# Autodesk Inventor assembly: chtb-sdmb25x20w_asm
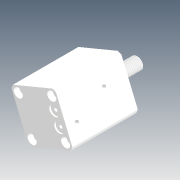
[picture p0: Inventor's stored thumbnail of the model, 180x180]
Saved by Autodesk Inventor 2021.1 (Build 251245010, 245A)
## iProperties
Company: Microsoft
Created: 2018-05
Part Number: chtb-sdmb25x20w_asm
Description: STEP AP214
Document SubType Name: Assembly
Designer: user
Title: chtb-sdmb25x20w_asm.STEP
Author: Windows
Revision Number: ÈÎºÎ
Sending System: SolidWorks 2015
Preprocessor: SwSTEP 2.0
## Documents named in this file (4)
- D:\Vault_2016\Projekty\Clamptek\Hydraulic\CHTB\CHTB-25\Inventor\chtb-sdmb25x20w\chtb-sdmb25x20w_asm.iam
- D:\Vault_2016\Projekty\Clamptek\Hydraulic\CHTB\CHTB-25\Inventor\chtb-sdmb25x20w\CHTB-25QG.ipt
- D:\Vault_2016\Projekty\Clamptek\Hydraulic\CHTB\CHTB-25\Inventor\chtb-sdmb25x20w\CHTB-SDMB25X20NBT.ipt
- D:\Vault_2016\Projekty\Clamptek\Hydraulic\CHTB\CHTB-25\Inventor\chtb-sdmb25x20w\CHTB-SDMB25X20WHSG.ipt
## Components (3 placed, 3 different names)
1. CHTB-25QG_1
2. CHTB-SDMB25X20NBT_2
3. CHTB-SDMB25X20WHSG_3
